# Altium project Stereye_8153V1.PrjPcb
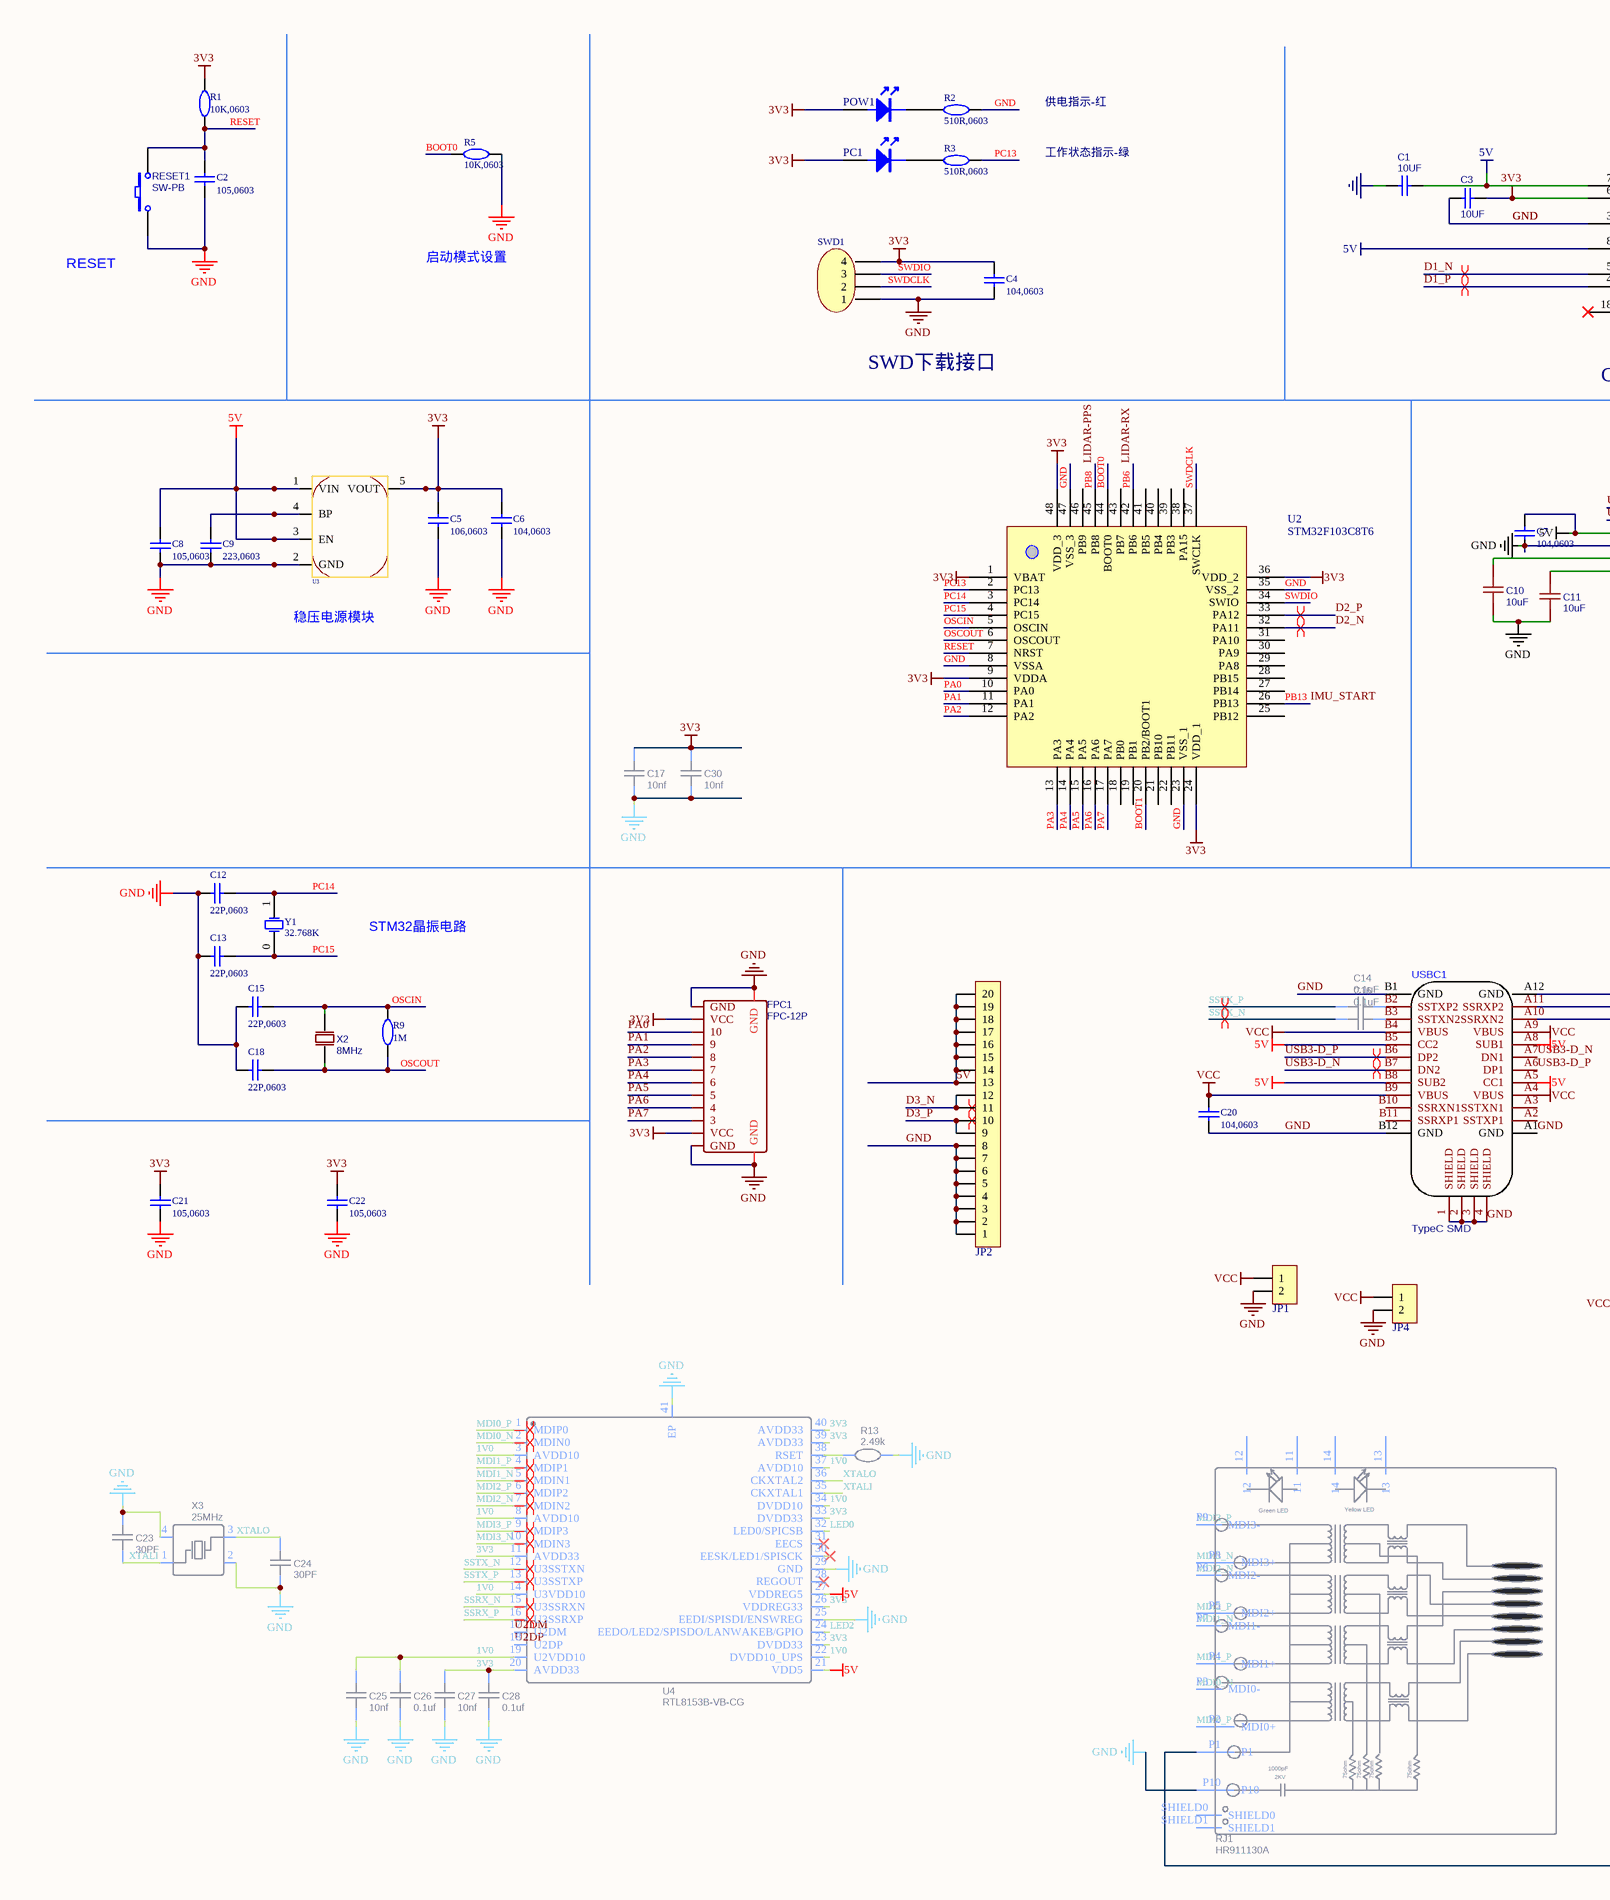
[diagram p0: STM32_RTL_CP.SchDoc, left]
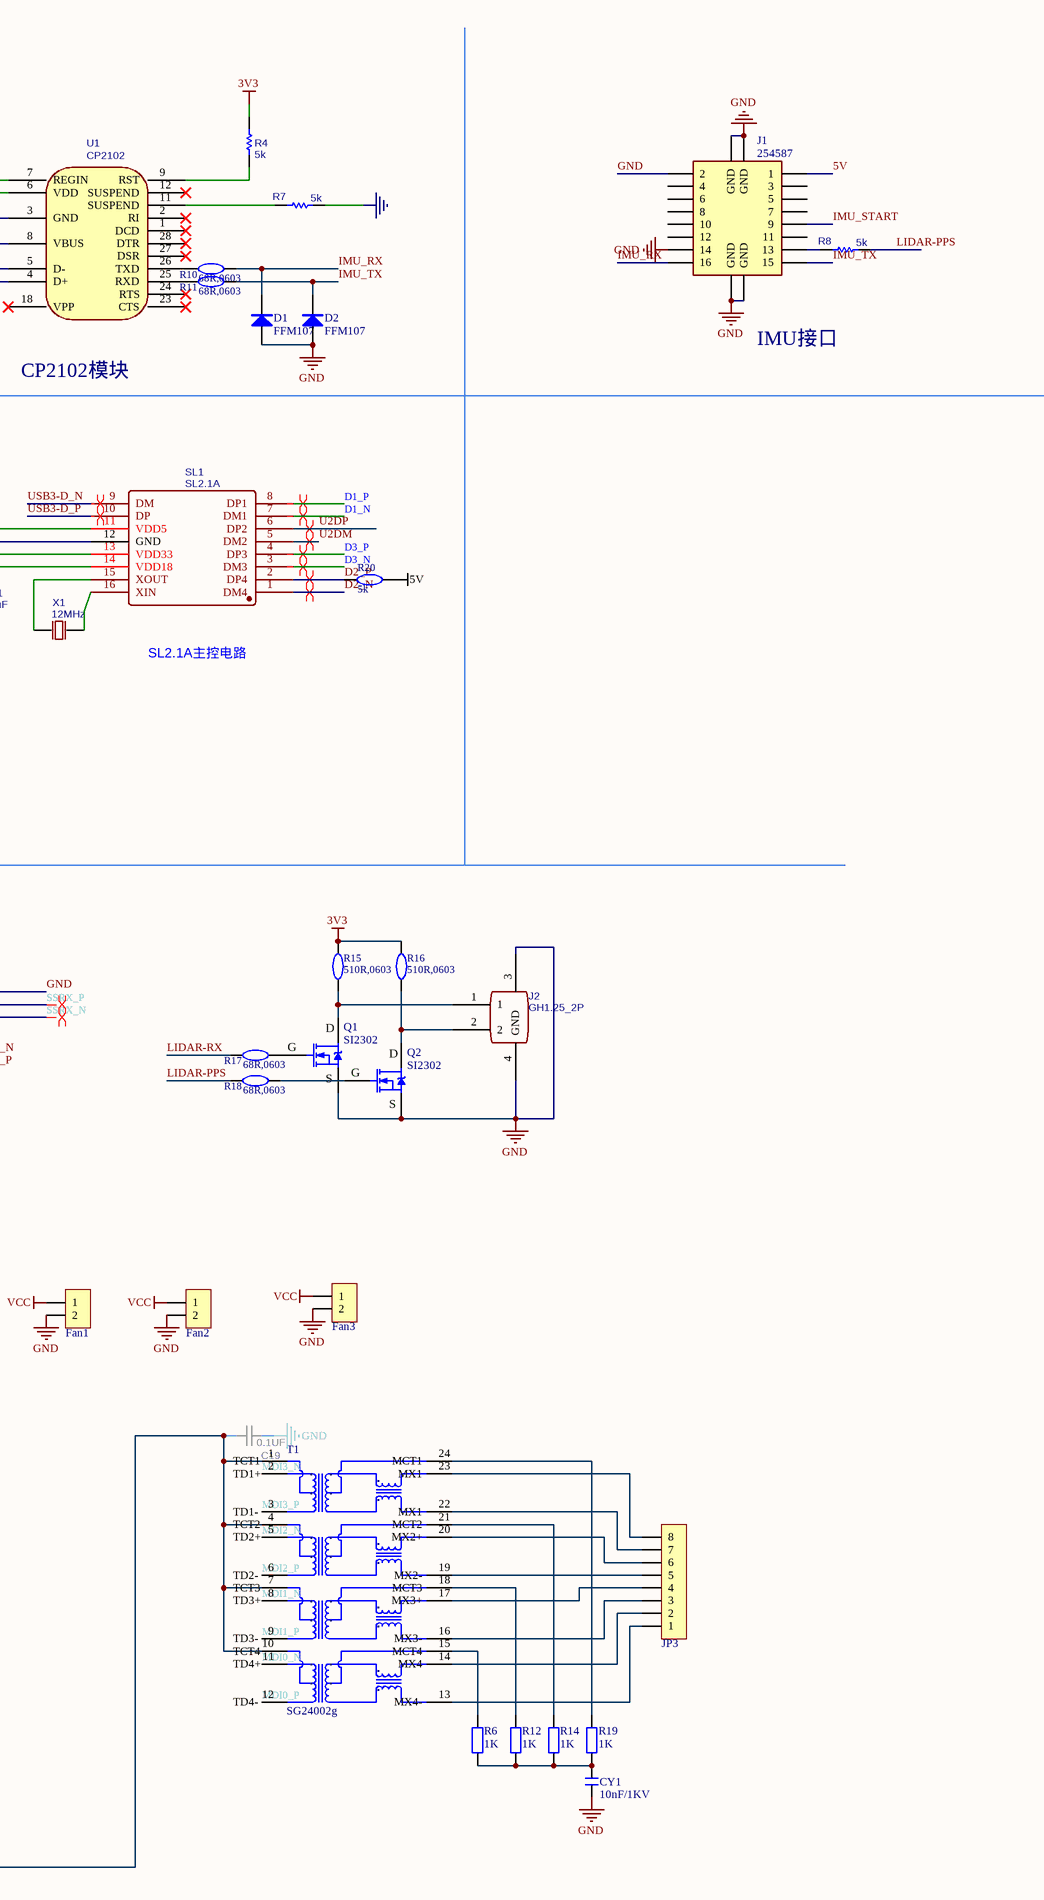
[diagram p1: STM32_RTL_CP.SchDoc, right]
1 sheet, 80 parts. Net scope: global (net labels, ports and power ports of the same name join across sheets).
Board file: STM32_RTL_CP.PcbDoc

## Sheet STM32_RTL_CP.SchDoc
size A2

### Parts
C1  10UF  [C0402_NEW]
C2  105  [C0402_NEW]  (value not drawn)
C3  10UF  [C0402_NEW]
C4  104  [C0402_NEW]  (value not drawn)
C5  106  [C0402_NEW]  (value not drawn)
C6  104  [C0402_NEW]  (value not drawn)
C7  104  [C0402_NEW]  (value not drawn)
C8  105  [C0402_NEW]  (value not drawn)
C9  223  [C0402_NEW]  (value not drawn)
C10  10uF  [C0402_NEW]
C11  10uF  [C0402_NEW]
C12  22P  [C0402_NEW]  (value not drawn)
C13  22P  [C0402_NEW]  (value not drawn)
C14  0.1uF  [C0402_NEW]
C15  22P  [C0402_NEW]  (value not drawn)
C16  0.1uF  [C0402_NEW]
C17  10nf  [C0402_NEW]
C18  22P  [C0402_NEW]  (value not drawn)
C19  0.1UF  [C0402_NEW]
C20  104  [C 1210_L]  (value not drawn)
C21  105  [C0402_NEW]  (value not drawn)
C22  105  [C0402_NEW]  (value not drawn)
C23  30PF  [C0402_NEW]
C24  30PF  [C0402_NEW]
C25  10nf  [C0402_NEW]
C26  0.1uf  [C0402_NEW]
C27  10nf  [C0402_NEW]
C28  0.1uf  [C0402_NEW]
C30  10nf  [C0402_NEW]
CY1  10nF/1KV  [C 1206_L]
D1  FFM107  [SOD-123F]
D2  FFM107  [SOD-123F]
Fan1  HDR-1X2  [PH2.0-WS-2P]  (value not drawn)
Fan2  HDR-1X2  [PH2.0-WS-2P]  (value not drawn)
Fan3  HDR-1X2  [PH2.0-WS-2P]  (value not drawn)
FPC1  FPC-12P  [FPC-0.5MM-12P]
J1  254587  [MH-16]
J2  GH1.25_2P  [GH1.25_2P]
JP1  HDR-1X2  [XT30]  (value not drawn)
JP2  HDR-1X20  [FPC0.5 2H-WS-20P]  (value not drawn)
JP3  HDR-1X8  [MX 1.25-WS-8P]  (value not drawn)
JP4  HDR-1X2  [MX 1.25-WS-2P]  (value not drawn)
PC1  LEDgreen  [LED]  (value not drawn)
POW1  LEDred  [LED]  (value not drawn)
Q1  SI2302  [SOT23-3N]
Q2  SI2302  [SOT23-3N]
R1  10K,0603  [C0402_NEW]
R2  510R,0603  [C0402_NEW]
R3  510R,0603  [C0402_NEW]
R4  5k  [C0402_NEW]
R5  10K,0603  [6-0805_N]
R6  1K  [R 0603_L]
R7  5k  [C0402_NEW]
R8  5k  [C0402_NEW]
R9  1M  [6-0805_N]
R10  68R,0603  [R0603_NEW]
R11  68R,0603  [R0603_NEW]
R12  1K  [R 0603_L]
R13  2.49k  [R0603_NEW]
R14  1K  [R 0603_L]
R15  510R,0603  [C0402_NEW]
R16  510R,0603  [C0402_NEW]
R17  68R,0603  [C0402_NEW]
R18  68R,0603  [C0402_NEW]
R19  1K  [R 0603_L]
R20  5k  [C0402_NEW]
RESET1  SW-PB  [Key]
RJ1  HR911130A  [RJ45-TH_HR911130A - duplicate]
SL1  SL2.1A  [SOP-16_L10.0-W3.9-P1.27-LS6.0-BL]
SWD1  SWD  [HDR1X4H]  (value not drawn)
T1  SG24002g  [SG24002]
U1  CP2102  [CP2102-28G]
U2  STM32F103C8T6  [STM32-48P]
U3  RT9193-33GB  [SOT-23-5]  (value not drawn)
U4  RTL8153B-VB-CG  [QFN-40_L5.0-W5.0-P0.40-BL-EP3.7]
USBC1  TypeC SMD  [USB-C-SMD_MC-312D-C]
X1  12MHz  [OSC HC-49SMD]
X2  8MHz  [OSC HC-49SMD]
X3  25MHz  [OSC-SMD_4P-L3.2-W2.5-BL]
Y1  32.768K  [XLAT-32]

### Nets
3V3: C3.2 C4.2 C5.1 C6.2 C17.2 C21.2 C22.2 C27.2 C28.2 C30.2 FPC1.2(VCC) FPC1.11(VCC) PC1.A POW1.A R1.2 R4.2 R15.2 R16.2 SWD1.4 U1.6(VDD) U2.1(VBAT) U2.9(VDDA) U2.24(VDD_1) U2.36(VDD_2) U2.48(VDD_3) U3.5(VOUT) U4.11(AVDD33) U4.20(AVDD33) U4.23(DVDD33) U4.26(VDDREG33) U4.33(DVDD33) U4.39(AVDD33) U4.40(AVDD33)
5V: C1.1 C7.2 C8.2 J1.B8(1) JP2.13 JP2.14 JP2.15 JP2.16 JP2.17 JP2.18 JP2.19 JP2.20 R20.1 SL1.11(VDD5) U1.7(REGIN) U1.8(VBUS) U3.1(VIN) U3.3(EN) U4.21(VDD5) U4.27(VDDREG5) USBC1.A5(CC1) USBC1.A8(SUB1) USBC1.B5(CC2) USBC1.B8(SUB2)
GND: C1.2 C2.1 C3.1 C4.1 C5.2 C6.1 C7.1 C8.1 C9.1 C10.1 C11.1 C12.2 C13.2 C15.2 C17.1 C18.2 C19.2 C20.1 C21.1 C22.1 C23.2 C24.1 C25.1 C26.1 C27.1 C28.1 C30.1 CY1.1 D1.1(A) D2.1(A) Fan1.2 Fan2.2 Fan3.2 FPC1.1(GND) FPC1.12(GND) FPC1.13(GND) FPC1.14(GND) J1.A2(14) J1.A8(2) J1.MP1(GND) J1.MP2(GND) J1.MP3(GND) J1.MP4(GND) J2.3 J2.4(GND) JP1.2 JP2.1 JP2.2 JP2.3 JP2.4 JP2.5 JP2.6 JP2.7 JP2.8 JP4.2 Q1.2(S) Q2.2(S) R2.2 R5.2 R7.2 R13.2 RESET1.1 RJ1.P10 SL1.12(GND) SWD1.1 U1.3(GND) U2.8(VSSA) U2.23(VSS_1) U2.35(VSS_2) U2.47(VSS_3) U3.2(GND) U4.25(EEDI/SPISDI/ENSWREG) U4.29(GND) U4.41(EP) USBC1.1(SHIELD) USBC1.2(SHIELD) USBC1.3(SHIELD) USBC1.4(SHIELD) USBC1.A1(GND) USBC1.A12(GND) USBC1.B1(GND) USBC1.B12(GND) X3.2(GND) X3.4(GND)
VCC: C20.2 Fan1.1 Fan2.1 Fan3.1 JP1.1 JP4.1 USBC1.A4(VBUS) USBC1.A9(VBUS) USBC1.B4(VBUS) USBC1.B9(VBUS)
1V0: C25.2 C26.2 U4.3(AVDD10) U4.8(AVDD10) U4.14(U3VDD10) U4.19(U2VDD10) U4.22(DVDD10_UPS) U4.34(DVDD10) U4.37(AVDD10)
BOOT0: R5.1 U2.44(BOOT0)
BOOT1: U2.20(PB2/BOOT1)
D1_N: SL1.7(DM1) U1.5(D-)
D1_P: SL1.8(DP1) U1.4(D+)
D2_N: SL1.1(DM4) U2.32(PA11)
D2_P: R20.2 SL1.2(DP4) U2.33(PA12)
D3_N: JP2.11 JP2.12 SL1.3(DM3)
D3_P: JP2.9 JP2.10 SL1.4(DP3)
IMU_RX: D1.2(K) J1.A1(16) R10.1
IMU_START: J1.B4(9) U2.26(PB13)  [also labelled PB13]
IMU_TX: D2.2(K) J1.B1(15) R11.1
LED0: U4.32(LED0/SPICSB)
LED2: U4.24(EEDO/LED2/SPISDO/LANWAKEB/GPIO)
LIDAR-PPS: R8.2 R18.2 U2.45(PB8)  [also labelled PB8]
LIDAR-RX: R17.2 U2.42(PB6)  [also labelled PB6]
MDI0_N: RJ1.P3(MDI0-) T1.11(TD4+) U4.2(MDIN0)
MDI0_P: RJ1.P2(MDI0+) T1.12(TD4-) U4.1(MDIP0)
MDI1_N: RJ1.P7(MDI1-) T1.8(TD3+) U4.5(MDIN1)
MDI1_P: RJ1.P4(MDI1+) T1.9(TD3-) U4.4(MDIP1)
MDI2_N: RJ1.P6(MDI2-) T1.5(TD2+) U4.7(MDIN2)
MDI2_P: RJ1.P5(MDI2+) T1.6(TD2-) U4.6(MDIP2)
MDI3_N: RJ1.P8(MDI3+) T1.2(TD1+) U4.10(MDIN3)
MDI3_P: RJ1.P9(MDI3-) T1.3(TD1-) U4.9(MDIP3)
OSCIN: C15.1 R9.2 U2.5(OSCIN) X2.2(OSC2)
OSCOUT: C18.1 R9.1 U2.6(OSCOUT) X2.1(OSC1)
PA0: FPC1.10 U2.10(PA0)
PA1: FPC1.9 U2.11(PA1)
PA2: FPC1.8 U2.12(PA2)
PA3: FPC1.7 U2.13(PA3)
PA4: FPC1.6 U2.14(PA4)
PA5: FPC1.5 U2.15(PA5)
PA6: FPC1.4 U2.16(PA6)
PA7: FPC1.3 U2.17(PA7)
PC13: R3.2 U2.2(PC13)
PC14: C12.1 U2.3(PC14) Y1.1(OSC2)
PC15: C13.1 U2.4(PC15) Y1.0(OSC1)
RESET: C2.2 R1.1 RESET1.2 U2.7(NRST)
SSRX_N: U4.15(U3SSRXN) USBC1.A10(SSRXN2)
SSRX_P: U4.16(U3SSRXP) USBC1.A11(SSRXP2)
SSTX_N: C16.1 U4.12(U3SSTXN)
SSTX_P: C14.1 U4.13(U3SSTXP)
SWDCLK: SWD1.2 U2.37(SWCLK)
SWDIO: SWD1.3 U2.34(SWIO)
U2DM: SL1.5(DM2) U4.17(U2DM)
U2DP: SL1.6(DP2) U4.18(U2DP)
USB3-D_N: SL1.9(DM) USBC1.A7(DN1) USBC1.B7(DN2)
USB3-D_P: SL1.10(DP) USBC1.A6(DP1) USBC1.B6(DP2)
XTALI: C23.1 U4.35(CKXTAL1) X3.1(OSC1)
XTALO: C24.2 U4.36(CKXTAL2) X3.3(OSC2)
NetC9_2: C9.2 U3.4(BP)
NetC10_2: C10.2 SL1.13(VDD33)
NetC11_2: C11.2 SL1.14(VDD18)
NetC14_2: C14.2 USBC1.B2(SSTXP2)
NetC16_2: C16.2 USBC1.B3(SSTXN2)
NetC19_1: C19.1 RJ1.P1 T1.1(TCT1) T1.4(TCT2) T1.7(TCT3) T1.10(TCT4)
NetCY1_2: CY1.2 R6.1 R12.1 R14.1 R19.1
NetJ1_B2: J1.B2(13) R8.1
NetJ2_1: J2.1 Q1.3(D) R15.1
NetJ2_2: J2.2 Q2.3(D) R16.1
NetJP3_1: JP3.1 T1.13(MX4-)
NetJP3_2: JP3.2 T1.14(MX4)
NetJP3_3: JP3.3 T1.16(MX3-)
NetJP3_4: JP3.4 T1.17(MX3+)
NetJP3_5: JP3.5 T1.19(MX2-)
NetJP3_6: JP3.6 T1.20(MX2+)
NetJP3_7: JP3.7 T1.22(MX1)
NetJP3_8: JP3.8 T1.23(MX1)
NetPC1_K: PC1.K R3.1
NetPOW1_K: POW1.K R2.1
NetQ1_1: Q1.1(G) R17.1
NetQ2_1: Q2.1(G) R18.1
NetR4_1: R4.1 U1.9(RST)
NetR6_2: R6.2 T1.15(MCT4)
NetR7_1: R7.1 U1.11(SUSPEND)
NetR10_2: R10.2 U1.26(TXD)
NetR11_2: R11.2 U1.25(RXD)
NetR12_2: R12.2 T1.18(MCT3)
NetR13_1: R13.1 U4.38(RSET)
NetR14_2: R14.2 T1.21(MCT2)
NetR19_2: R19.2 T1.24(MCT1)
NetSL1_15: SL1.15(XOUT) X1.2(OSC2)
NetSL1_16: SL1.16(XIN) X1.1(OSC1)

Not connected (* = marked no-connect by the designer): J1 A3(12) A4(10) A5(8) A6(6) A7(4) B3(11) B5(7) B6(5) B7(3); RJ1 11 12 13 14 SHIELD0 SHIELD1; U1 1(DCD)* 2(RI)* 12(SUSPEND)* 18(VPP)* 23(CTS)* 24(RTS)* 27(DSR)* 28(DTR)*; U2 18(PB0) 19(PB1) 21(PB10) 22(PB11) 25(PB12) 27(PB14) 28(PB15) 29(PA8) 30(PA9) 31(PA10) 38(PA15) 39(PB3) 40(PB4) 41(PB5) 43(PB7) 46(PB9); U4 28(REGOUT)* 30(EESK/LED1/SPISCK)* 31(EECS)*; USBC1 A2(SSTXP1) A3(SSTXN1) B10(SSRXN1) B11(SSRXP1)

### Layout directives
differential pair: (no net found under the mark), D1_N, D1_P, D2_N, D2_P, D3_N, D3_P, MDI0_N, MDI0_P, MDI1_N, MDI1_P, MDI2_N, MDI2_P, MDI3_N, MDI3_P, SSRX_N, SSRX_P, SSTX_N, SSTX_P, U2DM, U2DP, USB3-D_N, USB3-D_P

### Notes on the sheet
- 供电指示-红
- 工作状态指示-绿
- RESET
- 启动模式设置
- SWD下载接口
- CP2102模块
- IMU接口
- (near U3) 稳压电源模块
- SL2.1A主控电路
- STM32晶振电路

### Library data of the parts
C1 C3 = 47uf: catid: 20; sourceId: aYgasJ1jB
C2 C8 C21 C22 = 105: BOM_Manufacturer: YAGEO; BOM_Manufacturer Part: CC0603KRX7R9BB104
C4 C6 C7 C20 = 104: BOM_Manufacturer: YAGEO; BOM_Manufacturer Part: CC0603KRX7R9BB104
C5 = 106: BOM_Manufacturer: YAGEO; BOM_Manufacturer Part: CC0603KRX7R9BB104
C9 = 223: BOM_Manufacturer: YAGEO; BOM_Manufacturer Part: CC0603KRX7R9BB104
C10 C11 = 10uF: BOM_Manufacturer: SAMSUNG; BOM_Manufacturer Part: CL10A106MP8NNNC; nameAlias: Capacitance
C12 C13 C15 C18 = 22P: BOM_Manufacturer: YAGEO; BOM_Manufacturer Part: CC0603KRX7R9BB104
C14 C16 = 0.1uF: nameAlias: Value(F); Contributor: LCEDA_Lib
C17 C25 C27 C30 = 10nf: nameAlias: Value(F); Contributor: LCEDA_Lib
C19 = 0.1UF: nameAlias: Value(F); Contributor: LCEDA_Lib
C23 C24 = 30PF: nameAlias: Value(F); Contributor: LCEDA_Lib
C26 C28 = 0.1uf: nameAlias: Value(F); Contributor: LCEDA_Lib
CY1 = CY: 安规Y电容; BOM名称: 高压陶瓷电容，Y电容; 版权归属: 封装库来自淘宝 ID：黄晶宝石
D1 D2 = FFM107: 快恢复整流二极管; BOM名称: 快恢复二极管; 版权归属: 封装库来自淘宝 ID：黄晶宝石
Fan1-Fan3 JP1 JP4 = Header 2: 2P接插件; 版权归属: 封装库来自淘宝 ID：黄晶宝石
FPC1 = FPC-12P: BOM_Manufacturer: JUSHUO; BOM_Manufacturer Part: AFC01-S12FCA-00; Contributor: zhqtl2002
J1 = 254587: Connector; Manufacturer_Name: ERNI
J2 = GH1.25_2P: Contributor: AKER
JP2 = Header 20: 20P接插件; 版权归属: 封装库来自淘宝 ID：黄晶宝石
JP3 = Header 8: 8P接插件; 版权归属: 封装库来自淘宝 ID：黄晶宝石
PC1 POW1 = LED: pin to pad: A>1 K>2
Q1 Q2 = SI2302: N沟道场效应管
R1 R5 = 10K,0603: BOM_Manufacturer: UniOhm; BOM_Manufacturer Part: 060300J0103T5E
R2 R3 R10 R11 R15-R18 R20 = 510R,0603: BOM_Manufacturer: UniOhm; BOM_Manufacturer Part: 0603WAJ0511T5E
R4 R7 R8 = 5k: catid: 20; sourceId: RoYWUgdzx
R6 R12 R14 R19 = R: 贴片电阻; 版权归属: 来自淘宝 ID：黄晶宝石
R9 = 1M0603: BOM_Manufacturer: Uniroyal Elec; BOM_Manufacturer Part: 0603WAF1054T5E
R13 = 2.49k: nameAlias: Value(Ω); Contributor: LCEDA_Lib
RESET1 = SW-PB: Contributor: liujiayu6388
RJ1 = HR911130A: BOM_Manufacturer: HANRUN
SL1 = SL2.1A: BOM_Manufacturer: CoreChips; Contributor: LCSC; SMT Type: Extend
SWD1 = SWD: BOM_Manufacturer: Ckmtw; BOM_Manufacturer Part: 210S-1*4P L=11.6MMGold-plated black
U1 = CP2102: catid: 20; sourceId: 1y8642nlj
U3 = RT9193-33GB: ICA_MFR_NAME: RICHTEK; ICA_PARTNUM: $$2191094$$RT9193-15CU5; Part Number: TMP-13
U4 = RTL8153B-VB-CG: BOM_Manufacturer: REALTEK(瑞昱); Contributor: LCSC
X1 = 12MHz: BOM_Manufacturer: YXC; BOM_Manufacturer Part: X49SD12MSD2SC; nameAlias: Frequency
X2 = 8MHz: BOM_Manufacturer: ZheJiang East Crystal Elec; BOM_Manufacturer Part: B08000J065; nameAlias: Frequency; Contributor: LCSC
X3 = 25MHz: BOM_Manufacturer: Zhejiang Abel Elec; BOM_Manufacturer Part: SMD-3225_4P25MHZ12PF10PPM-40~+85℃; nameAlias: Frequency; Contributor: LCSC; SMT Type: Extend
Y1 = XLAT-32: BOM_Manufacturer: KDS; BOM_Manufacturer Part: DST310S 32.768KHz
